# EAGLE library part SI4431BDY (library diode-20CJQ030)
Vishay Siliconix Si4431BDY P-Channel 30-V (D-S) MOSFET Please send any comments to: messi@users.sourceforge.net
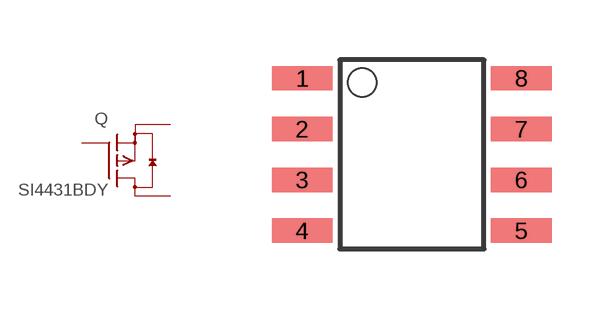
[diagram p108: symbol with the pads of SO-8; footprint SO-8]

Designator prefix Q

## SI4431BDY  [SO-8]
1  S  pas
2  S  pas
3  S  pas
4  G  pas
5  D  pas
6  D  pas
7  D  pas
8  D  pas

## Footprint SO-8 (pad centres in mm)
small outline
smd 1.524 x 0.61: 1 -2.743,1.27; 2 -2.743,0; 3 -2.743,-1.27; 4 -2.743,-2.54; 5 2.743,-2.54; 6 2.743,-1.27; 7 2.743,0; 8 2.743,1.27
